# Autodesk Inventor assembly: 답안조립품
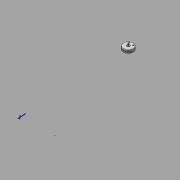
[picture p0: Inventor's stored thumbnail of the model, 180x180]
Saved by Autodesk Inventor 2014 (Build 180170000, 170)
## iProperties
Created: 2015-06
Part Number: 답안조립품
Document SubType Name: Assembly
Designer: MYHOME
Author: MYHOME
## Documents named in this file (10)
- C:\Documents and Settings\MYHOME\바탕 화면\450631V1046\답안조립품.iam
- C:\Documents and Settings\MYHOME\바탕 화면\450631V1046\본체.ipt
- C:\Documents and Settings\MYHOME\바탕 화면\450631V1046\베어링62_22.ipt
- C:\Documents and Settings\MYHOME\바탕 화면\450631V1046\덮개.ipt
- C:\Documents and Settings\MYHOME\바탕 화면\450631V1046\축.ipt
- C:\Documents and Settings\MYHOME\바탕 화면\450631V1046\멈춤링.ipt
- C:\Documents and Settings\MYHOME\바탕 화면\450631V1046\슬라이더2.ipt
- C:\Documents and Settings\MYHOME\바탕 화면\450631V1046\슬라이더.ipt
- C:\Documents and Settings\MYHOME\바탕 화면\450631V1046\평행핀.ipt
- C:\Documents and Settings\MYHOME\바탕 화면\450631V1046\M10x35.ipt
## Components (7 placed, 4 different names)
1. KS B 2023 62/22 - 22 x 50 x 14:2
2. KS B 1336 22 x 1.2:1
3. KS B 1336 22 x 1.2:2
4. KS B 2023 62/22 - 22 x 50 x 14:3
5. KS B 1320 B B 5 x  20:1
6. KS B 1003 - 미터 M 10 x 35:1
7. KS B 1003 - 미터 M 10 x 35:2
